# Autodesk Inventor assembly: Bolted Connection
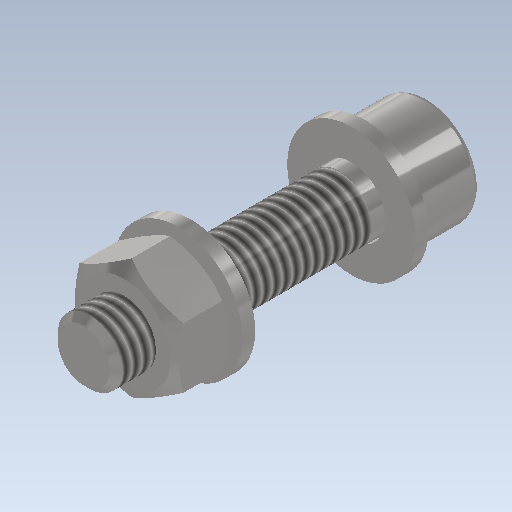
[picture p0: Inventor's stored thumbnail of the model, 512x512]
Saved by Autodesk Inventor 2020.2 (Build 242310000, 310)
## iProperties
ClientObjectVersion: 1
Created: 2020-01
Part Number: Bolted Connection
Document SubType Name: Assembly
Designer: thira
Author: thira
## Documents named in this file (4)
- C:\Users\thira\OneDrive\เดสก์ท็อป\INV-01 Intro to Modeling_2020\Wheel Assem Final V1\Wheel Assy_Joint\Design Accelerator\Bolted Connection1.iam
- C:\Users\thira\OneDrive\เอกสาร\Inventor\Content Center Files\R2020\en-US\ISO 7089\ISO 7089 - 8 - 140 HV(1).ipt
- C:\Users\thira\OneDrive\เอกสาร\Inventor\Content Center Files\R2020\en-US\ISO 4762(2)\ISO 4762 - M8 x 35ISO.ipt
- C:\Users\thira\OneDrive\เอกสาร\Inventor\Content Center Files\R2020\en-US\ISO 4032(2)\ISO 4032 - M8 - ISO.ipt
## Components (4 placed, 3 different names)
1. ISO 7089 8:1
2. ISO 4762 M8 x 35:1
3. ISO 7089 8:2
4. ISO 4032 M8:1
